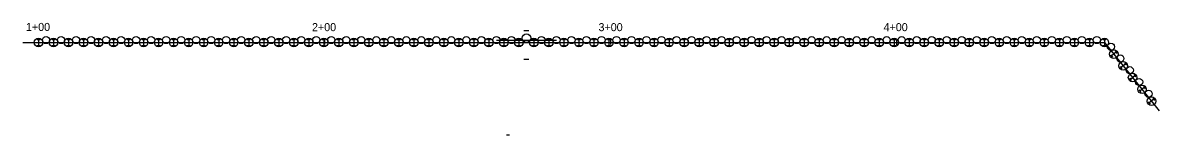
# Model space of a CAD drawing. Extents: x -2280229 to 1306, y -58886 to 440.
# Drawn here: x 908 to 1305.5, y -321.8 to -282.6 of the extents above; entities that cross this region are included whole.
import ezdxf

# ---------------------------------------------------------------- set-up
doc = ezdxf.new("R2010")
doc.units = 0
for name, color, linetype in [('BR_P_Beam_Stl_Det', 7, 'Continuous'), ('BR_P_Det_Object', 7, 'Continuous'), ('BR_P_Gen_Centerline', 7, 'Continuous'), ('BR_P_Sub_Deep_Object', 7, 'Continuous'), ('DR_X_Underdrain', 7, 'Continuous'), ('SC_Scratch9', 7, 'Continuous')]:
    doc.layers.add(name, color=color, linetype=linetype)

msp = doc.modelspace()

# ---------------------------------------------------------------- linework, layer by layer
at = {"layer": 'BR_P_Beam_Stl_Det'}
for p, q in [((913.04, -288.45), (914.11, -288.45)), ((913.58, -288.45), (913.58, -290.49)), ((918.29, -288.45), (919.36, -288.45)), ((918.83, -288.45), (918.83, -290.49)), ((923.54, -288.45), (924.61, -288.45)), ((924.08, -288.45), (924.08, -290.49)), ((928.79, -288.45), (929.86, -288.45)), ((929.33, -288.45), (929.33, -290.49)), ((934.04, -288.45), (935.11, -288.45)), ((934.58, -288.45), (934.58, -290.49)), ((939.29, -288.45), (940.36, -288.45)), ((939.83, -288.45), (939.83, -290.49)), ((944.54, -288.45), (945.61, -288.45)), ((945.08, -288.45), (945.08, -290.49)), ((949.79, -288.45), (950.86, -288.45)), ((950.33, -288.45), (950.33, -290.49)), ((955.04, -288.45), (956.11, -288.45)), ((955.58, -288.45), (955.58, -290.49)), ((960.29, -288.45), (961.36, -288.45)), ((960.83, -288.45), (960.83, -290.49)), ((965.54, -288.45), (966.61, -288.45)), ((966.08, -288.45), (966.08, -290.49)), ((970.79, -288.45), (971.86, -288.45)), ((971.33, -288.45), (971.33, -290.49)), ((976.04, -288.45), (977.11, -288.45)), ((976.58, -288.45), (976.58, -290.49)), ((981.29, -288.45), (982.36, -288.45)), ((981.83, -288.45), (981.83, -290.49)), ((986.54, -288.45), (987.61, -288.45)), ((987.08, -288.45), (987.08, -290.49)), ((991.79, -288.45), (992.86, -288.45)), ((992.33, -288.45), (992.33, -290.49)), ((997.04, -288.45), (998.11, -288.45)), ((997.58, -288.45), (997.58, -290.49)), ((1002.29, -288.45), (1003.36, -288.45)), ((1002.83, -288.45), (1002.83, -290.49)), ((1007.54, -288.45), (1008.61, -288.45)), ((1008.08, -288.45), (1008.08, -290.49)), ((1012.79, -288.45), (1013.86, -288.45)), ((1013.33, -288.45), (1013.33, -290.49)), ((1018.04, -288.45), (1019.11, -288.45)), ((1018.58, -288.45), (1018.58, -290.49)), ((1023.29, -288.45), (1024.36, -288.45)), ((1023.83, -288.45), (1023.83, -290.49)), ((1028.54, -288.45), (1029.61, -288.45)), ((1029.08, -288.45), (1029.08, -290.49)), ((1033.79, -288.45), (1034.86, -288.45)), ((1034.33, -288.45), (1034.33, -290.49)), ((1039.04, -288.45), (1040.11, -288.45)), ((1039.58, -288.45), (1039.58, -290.49)), ((1044.29, -288.45), (1045.36, -288.45)), ((1044.83, -288.45), (1044.83, -290.49)), ((1049.54, -288.45), (1050.61, -288.45)), ((1050.08, -288.45), (1050.08, -290.49)), ((1054.79, -288.45), (1055.86, -288.45)), ((1055.33, -288.45), (1055.33, -290.49)), ((1060.04, -288.45), (1061.11, -288.45)), ((1060.58, -288.45), (1060.58, -290.49)), ((1065.29, -288.45), (1066.36, -288.45)), ((1065.83, -288.45), (1065.83, -290.49)), ((1070.54, -288.45), (1071.61, -288.45)), ((1071.08, -288.45), (1071.08, -290.49)), ((1075.79, -288.45), (1076.86, -288.45)), ((1076.33, -288.45), (1076.33, -290.49)), ((1081.04, -288.45), (1082.11, -288.45)), ((1081.58, -288.45), (1081.58, -290.49)), ((1086.29, -288.45), (1087.36, -288.45)), ((1086.83, -288.45), (1086.83, -290.49)), ((1091.54, -288.45), (1092.61, -288.45)), ((1092.08, -288.45), (1092.08, -290.49)), ((1096.79, -288.45), (1097.86, -288.45)), ((1097.33, -288.45), (1097.33, -290.49)), ((1102.04, -288.45), (1103.11, -288.45)), ((1102.58, -288.45), (1102.58, -290.49)), ((1107.29, -288.45), (1108.36, -288.45)), ((1107.83, -288.45), (1107.83, -290.49)), ((1112.54, -288.45), (1113.61, -288.45)), ((1113.08, -288.45), (1113.08, -290.49)), ((1117.79, -288.45), (1118.86, -288.45)), ((1118.33, -288.45), (1118.33, -290.49)), ((1123.04, -288.45), (1124.11, -288.45)), ((1123.58, -288.45), (1123.58, -290.49)), ((1128.29, -288.45), (1129.36, -288.45)), ((1128.83, -288.45), (1128.83, -290.49)), ((1133.54, -288.45), (1134.61, -288.45)), ((1134.08, -288.45), (1134.08, -290.49)), ((1138.79, -288.45), (1139.86, -288.45)), ((1139.33, -288.45), (1139.33, -290.49)), ((1144.04, -288.45), (1145.11, -288.45)), ((1144.58, -288.45), (1144.58, -290.49)), ((1149.29, -288.45), (1150.36, -288.45)), ((1149.83, -288.45), (1149.83, -290.49)), ((1154.54, -288.45), (1155.61, -288.45)), ((1155.08, -288.45), (1155.08, -290.49)), ((1159.79, -288.45), (1160.86, -288.45)), ((1160.33, -288.45), (1160.33, -290.49)), ((1165.04, -288.45), (1166.11, -288.45)), ((1165.58, -288.45), (1165.58, -290.49)), ((1170.29, -288.45), (1171.36, -288.45)), ((1170.83, -288.45), (1170.83, -290.49)), ((1175.54, -288.45), (1176.61, -288.45)), ((1176.08, -288.45), (1176.08, -290.49)), ((1180.79, -288.45), (1181.86, -288.45)), ((1181.33, -288.45), (1181.33, -290.49)), ((1186.04, -288.45), (1187.11, -288.45)), ((1186.58, -288.45), (1186.58, -290.49)), ((1191.29, -288.45), (1192.36, -288.45)), ((1191.83, -288.45), (1191.83, -290.49)), ((1196.54, -288.45), (1197.61, -288.45)), ((1197.08, -288.45), (1197.08, -290.49)), ((1201.79, -288.45), (1202.86, -288.45)), ((1202.33, -288.45), (1202.33, -290.49)), ((1207.04, -288.45), (1208.11, -288.45)), ((1207.58, -288.45), (1207.58, -290.49)), ((1212.29, -288.45), (1213.36, -288.45)), ((1212.83, -288.45), (1212.83, -290.49)), ((1217.54, -288.45), (1218.61, -288.45)), ((1218.08, -288.45), (1218.08, -290.49)), ((1222.79, -288.45), (1223.86, -288.45)), ((1223.33, -288.45), (1223.33, -290.49)), ((1228.04, -288.45), (1229.11, -288.45)), ((1228.58, -288.45), (1228.58, -290.49)), ((1233.29, -288.45), (1234.36, -288.45)), ((1233.83, -288.45), (1233.83, -290.49)), ((1238.54, -288.45), (1239.61, -288.45)), ((1239.08, -288.45), (1239.08, -290.49)), ((1243.79, -288.45), (1244.86, -288.45)), ((1244.33, -288.45), (1244.33, -290.49)), ((1249.04, -288.45), (1250.11, -288.45)), ((1249.58, -288.45), (1249.58, -290.49)), ((1254.29, -288.45), (1255.36, -288.45)), ((1254.83, -288.45), (1254.83, -290.49)), ((1259.54, -288.45), (1260.61, -288.45)), ((1260.08, -288.45), (1260.08, -290.49)), ((1264.79, -288.45), (1265.86, -288.45)), ((1265.33, -288.45), (1265.33, -290.49)), ((1270.04, -288.45), (1271.11, -288.45)), ((1270.58, -288.45), (1270.58, -290.49)), ((1275.29, -288.45), (1276.36, -288.45)), ((1275.83, -288.45), (1275.83, -290.49)), ((1280.54, -288.45), (1281.61, -288.45)), ((1281.08, -288.45), (1281.08, -290.49)), ((1285.79, -288.45), (1286.86, -288.45)), ((1286.33, -288.45), (1286.33, -290.49)), ((913.04, -290.49), (914.11, -290.49)), ((918.29, -290.49), (919.36, -290.49)), ((923.54, -290.49), (924.61, -290.49)), ((928.79, -290.49), (929.86, -290.49)), ((934.04, -290.49), (935.11, -290.49)), ((939.29, -290.49), (940.36, -290.49)), ((944.54, -290.49), (945.61, -290.49)), ((949.79, -290.49), (950.86, -290.49)), ((955.04, -290.49), (956.11, -290.49)), ((960.29, -290.49), (961.36, -290.49)), ((965.54, -290.49), (966.61, -290.49)), ((970.79, -290.49), (971.86, -290.49)), ((976.04, -290.49), (977.11, -290.49)), ((981.29, -290.49), (982.36, -290.49)), ((986.54, -290.49), (987.61, -290.49)), ((991.79, -290.49), (992.86, -290.49)), ((997.04, -290.49), (998.11, -290.49)), ((1002.29, -290.49), (1003.36, -290.49)), ((1007.54, -290.49), (1008.61, -290.49)), ((1012.79, -290.49), (1013.86, -290.49)), ((1018.04, -290.49), (1019.11, -290.49)), ((1023.29, -290.49), (1024.36, -290.49)), ((1028.54, -290.49), (1029.61, -290.49)), ((1033.79, -290.49), (1034.86, -290.49)), ((1039.04, -290.49), (1040.11, -290.49)), ((1044.29, -290.49), (1045.36, -290.49)), ((1049.54, -290.49), (1050.61, -290.49)), ((1054.79, -290.49), (1055.86, -290.49)), ((1060.04, -290.49), (1061.11, -290.49)), ((1065.29, -290.49), (1066.36, -290.49)), ((1070.54, -290.49), (1071.61, -290.49)), ((1075.79, -290.49), (1076.86, -290.49)), ((1081.04, -290.49), (1082.11, -290.49)), ((1086.29, -290.49), (1087.36, -290.49)), ((1091.54, -290.49), (1092.61, -290.49)), ((1096.79, -290.49), (1097.86, -290.49)), ((1102.04, -290.49), (1103.11, -290.49)), ((1107.29, -290.49), (1108.36, -290.49)), ((1112.54, -290.49), (1113.61, -290.49)), ((1117.79, -290.49), (1118.86, -290.49)), ((1123.04, -290.49), (1124.11, -290.49)), ((1128.29, -290.49), (1129.36, -290.49)), ((1133.54, -290.49), (1134.61, -290.49)), ((1138.79, -290.49), (1139.86, -290.49)), ((1144.04, -290.49), (1145.11, -290.49)), ((1149.29, -290.49), (1150.36, -290.49)), ((1154.54, -290.49), (1155.61, -290.49)), ((1159.79, -290.49), (1160.86, -290.49)), ((1165.04, -290.49), (1166.11, -290.49)), ((1170.29, -290.49), (1171.36, -290.49)), ((1175.54, -290.49), (1176.61, -290.49)), ((1180.79, -290.49), (1181.86, -290.49)), ((1186.04, -290.49), (1187.11, -290.49)), ((1191.29, -290.49), (1192.36, -290.49)), ((1196.54, -290.49), (1197.61, -290.49)), ((1201.79, -290.49), (1202.86, -290.49)), ((1207.04, -290.49), (1208.11, -290.49)), ((1212.29, -290.49), (1213.36, -290.49)), ((1217.54, -290.49), (1218.61, -290.49)), ((1222.79, -290.49), (1223.86, -290.49)), ((1228.04, -290.49), (1229.11, -290.49)), ((1233.29, -290.49), (1234.36, -290.49)), ((1238.54, -290.49), (1239.61, -290.49)), ((1243.79, -290.49), (1244.86, -290.49)), ((1249.04, -290.49), (1250.11, -290.49)), ((1254.29, -290.49), (1255.36, -290.49)), ((1259.54, -290.49), (1260.61, -290.49)), ((1264.79, -290.49), (1265.86, -290.49)), ((1270.04, -290.49), (1271.11, -290.49)), ((1275.29, -290.49), (1276.36, -290.49)), ((1280.54, -290.49), (1281.61, -290.49)), ((1285.79, -290.49), (1286.86, -290.49)), ((1288.51, -293.75), (1289.18, -294.59)), ((1290.44, -292.89), (1288.84, -294.17)), ((1290.1, -292.47), (1290.77, -293.31)), ((1291.8, -297.85), (1292.47, -298.68)), ((1293.72, -296.99), (1292.13, -298.26)), ((1293.39, -296.57), (1294.06, -297.4)), ((1295.08, -301.94), (1295.75, -302.78)), ((1297.01, -301.08), (1295.42, -302.36)), ((1296.67, -300.66), (1297.35, -301.5)), ((1298.37, -306.03), (1299.04, -306.87)), ((1300.3, -305.17), (1298.71, -306.45)), ((1299.96, -304.75), (1300.63, -305.59)), ((1303.59, -309.27), (1301.99, -310.54)), ((1303.25, -308.85), (1303.92, -309.68)), ((1301.66, -310.13), (1302.33, -310.96))]:
    msp.add_line(p, q, dxfattribs=at)
at = {"layer": 'BR_P_Det_Object'}
for p, q in [((1083.32, -285.29), (1085.07, -285.29)), ((1083.33, -295.29), (1085.08, -295.29))]:
    msp.add_line(p, q, dxfattribs=at)
at = {"layer": 'BR_P_Gen_Centerline'}
for p, q in [((908.04, -289.47), (1286.33, -289.47)), ((1286.33, -289.47), (1305.53, -313.31))]:
    msp.add_line(p, q, dxfattribs=at)
at = {"layer": 'BR_P_Sub_Deep_Object'}
for centre, radius in [((913.58, -289.47), 1.5), ((916.2, -288.65), 1.25), ((918.83, -289.47), 1.5), ((921.45, -288.65), 1.25), ((924.08, -289.47), 1.5), ((926.7, -288.65), 1.25), ((929.33, -289.47), 1.5), ((931.95, -288.65), 1.25), ((934.58, -289.47), 1.5), ((937.2, -288.65), 1.25), ((939.83, -289.47), 1.5), ((942.45, -288.65), 1.25), ((945.08, -289.47), 1.5), ((947.7, -288.65), 1.25), ((950.33, -289.47), 1.5), ((952.95, -288.65), 1.25), ((955.58, -289.47), 1.5), ((958.2, -288.65), 1.25), ((960.83, -289.47), 1.5), ((963.45, -288.65), 1.25), ((966.08, -289.47), 1.5), ((968.7, -288.65), 1.25), ((971.33, -289.47), 1.5), ((973.95, -288.65), 1.25), ((976.58, -289.47), 1.5), ((979.2, -288.65), 1.25), ((981.83, -289.47), 1.5), ((984.45, -288.65), 1.25), ((987.08, -289.47), 1.5), ((989.7, -288.65), 1.25), ((992.33, -289.47), 1.5), ((994.95, -288.65), 1.25), ((997.58, -289.47), 1.5), ((1000.2, -288.65), 1.25), ((1002.83, -289.47), 1.5), ((1005.45, -288.65), 1.25), ((1008.08, -289.47), 1.5), ((1010.7, -288.65), 1.25), ((1013.33, -289.47), 1.5), ((1015.95, -288.65), 1.25), ((1018.58, -289.47), 1.5), ((1021.2, -288.65), 1.25), ((1023.83, -289.47), 1.5), ((1026.45, -288.65), 1.25), ((1029.08, -289.47), 1.5), ((1031.7, -288.65), 1.25), ((1034.33, -289.47), 1.5), ((1036.95, -288.65), 1.25), ((1039.58, -289.47), 1.5), ((1042.2, -288.65), 1.25), ((1044.83, -289.47), 1.5), ((1047.45, -288.65), 1.25), ((1050.08, -289.47), 1.5), ((1052.7, -288.65), 1.25), ((1055.33, -289.47), 1.5), ((1057.95, -288.65), 1.25), ((1060.58, -289.47), 1.5), ((1063.2, -288.65), 1.25), ((1065.83, -289.47), 1.5), ((1068.45, -288.65), 1.25), ((1071.08, -289.47), 1.5), ((1073.7, -288.65), 1.25), ((1076.33, -289.47), 1.5), ((1078.95, -288.65), 1.25), ((1081.58, -289.47), 1.5), ((1084.2, -288.02), 1.5), ((1086.83, -289.47), 1.5), ((1089.45, -288.65), 1.25), ((1092.08, -289.47), 1.5), ((1094.7, -288.65), 1.25), ((1097.33, -289.47), 1.5), ((1099.95, -288.65), 1.25), ((1102.58, -289.47), 1.5), ((1105.2, -288.65), 1.25), ((1107.83, -289.47), 1.5), ((1110.45, -288.65), 1.25), ((1113.08, -289.47), 1.5), ((1115.7, -288.65), 1.25), ((1118.33, -289.47), 1.5), ((1120.95, -288.65), 1.25), ((1123.58, -289.47), 1.5), ((1126.2, -288.65), 1.25), ((1128.83, -289.47), 1.5), ((1131.45, -288.65), 1.25), ((1134.08, -289.47), 1.5), ((1136.7, -288.65), 1.25), ((1139.33, -289.47), 1.5), ((1141.95, -288.65), 1.25), ((1144.58, -289.47), 1.5), ((1147.2, -288.65), 1.25), ((1149.83, -289.47), 1.5), ((1152.45, -288.65), 1.25), ((1155.08, -289.47), 1.5), ((1157.7, -288.65), 1.25), ((1160.33, -289.47), 1.5), ((1162.95, -288.65), 1.25), ((1165.58, -289.47), 1.5), ((1168.2, -288.65), 1.25), ((1170.83, -289.47), 1.5), ((1173.45, -288.65), 1.25), ((1176.08, -289.47), 1.5), ((1178.7, -288.65), 1.25), ((1181.33, -289.47), 1.5), ((1183.95, -288.65), 1.25), ((1186.58, -289.47), 1.5), ((1189.2, -288.65), 1.25), ((1191.83, -289.47), 1.5), ((1194.45, -288.65), 1.25), ((1197.08, -289.47), 1.5), ((1199.7, -288.65), 1.25), ((1202.33, -289.47), 1.5), ((1204.95, -288.65), 1.25), ((1207.58, -289.47), 1.5), ((1210.2, -288.65), 1.25), ((1212.83, -289.47), 1.5), ((1215.45, -288.65), 1.25), ((1218.08, -289.47), 1.5), ((1220.7, -288.65), 1.25), ((1223.33, -289.47), 1.5), ((1225.95, -288.65), 1.25), ((1228.58, -289.47), 1.5), ((1231.2, -288.65), 1.25), ((1233.83, -289.47), 1.5), ((1236.45, -288.65), 1.25), ((1239.08, -289.47), 1.5), ((1241.7, -288.65), 1.25), ((1244.33, -289.47), 1.5), ((1246.95, -288.65), 1.25), ((1249.58, -289.47), 1.5), ((1252.2, -288.65), 1.25), ((1254.83, -289.47), 1.5), ((1257.45, -288.65), 1.25), ((1260.08, -289.47), 1.5), ((1262.7, -288.65), 1.25), ((1265.33, -289.47), 1.5), ((1267.95, -288.65), 1.25), ((1270.58, -289.47), 1.5), ((1273.2, -288.65), 1.25), ((1275.83, -289.47), 1.5), ((1278.45, -288.65), 1.25), ((1281.08, -289.47), 1.5), ((1283.7, -288.65), 1.25), ((1286.33, -289.47), 1.5), ((1288.63, -290.97), 1.25), ((1289.64, -293.53), 1.5), ((1291.92, -295.07), 1.25), ((1292.93, -297.63), 1.5), ((1295.21, -299.16), 1.25), ((1296.21, -301.72), 1.5), ((1298.49, -303.25), 1.25), ((1299.5, -305.81), 1.5), ((1301.78, -307.35), 1.25), ((1302.79, -309.91), 1.5)]:
    msp.add_circle(centre, radius, dxfattribs=at)
at = {"layer": 'DR_X_Underdrain'}
msp.add_line((1078.29, -321.79), (1077.29, -321.79), dxfattribs=at)
at = {"layer": 'SC_Scratch9'}
for p, q in [((1013.58, -288.63), (1013.58, -290.21)), ((1073.7, -288.65), (1094.7, -288.65)), ((1113.58, -288.59), (1113.58, -290.23)), ((1213.58, -288.7), (1213.58, -290.31))]:
    msp.add_line(p, q, dxfattribs=at)

# ---------------------------------------------------------------- texts
for s, p in [('1+00', (909.17, -285.48)), ('2+00', (1009.21, -285.55)), ('3+00', (1109.42, -285.55)), ('4+00', (1209.11, -285.55))]:
    msp.add_text(s, height=2.8, rotation=0, dxfattribs=at).set_placement(p)

doc.saveas('drawing.dxf')
